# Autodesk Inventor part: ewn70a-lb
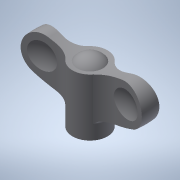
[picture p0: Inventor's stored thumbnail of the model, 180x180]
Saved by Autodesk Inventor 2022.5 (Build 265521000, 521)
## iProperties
Created: 2016-12
Part Number: ewn70a-lb
Material: 一般
Document SubType Name: Modeling
Designer: imaocorp
Density: 1 g/cm^3
Appearance: 既定
Author: imaocorp
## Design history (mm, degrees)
node "ewn70a-lb.x_t1"
node "ewn70a-lb"
node "Base1"
